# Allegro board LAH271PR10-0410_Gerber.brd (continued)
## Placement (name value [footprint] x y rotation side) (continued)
CT3  0.22U_0201_6.3V6K  [C_0201]  37.16 31.44 270 bottom
CT4  0.22U_0201_6.3V6K  [C_0201]  34.56 31.05 270 bottom
CT5  0.22U_0201_6.3V6K  [C_0201]  33.99 31.05 270 bottom
CT6  0.22U_0201_6.3V6K  [C_0201]  35.37 30.85 90 bottom
CT7  0.22U_0201_6.3V6K  [C_0201]  35.96 30.85 90 bottom
CT8  0.22U_0201_6.3V6K  [C_0201]  32.71 31.13 90 bottom
CT9  0.22U_0201_6.3V6K  [C_0201]  33.28 31.13 90 bottom
CT10  0.22U_0201_6.3V6K  [C_0201]  39.91 41.41 0 bottom
CT11  0.22U_0201_6.3V6K  [C_0201]  39.91 40.84 0 bottom
CT12  0.22U_0201_6.3V6K  [C_0201]  38.39 40.27 0 bottom
CT13  0.22U_0201_6.3V6K  [C_0201]  38.39 39.69 0 bottom
CT14  0.22U_0201_6.3V6K  [C_0201]  39.91 39.12 0 bottom
CT15  0.22U_0201_6.3V6K  [C_0201]  39.91 38.55 0 bottom
CT16  0.22U_0201_6.3V6K  [C_0201]  38.39 37.41 0 bottom
CT17  0.22U_0201_6.3V6K  [C_0201]  38.39 37.98 0 bottom
CT18  0.22U_0201_6.3V6K  [C_0201]  30.27 49.43 90 bottom
CT19  0.22U_0201_6.3V6K  [C_0201]  29.63 49.43 90 bottom
CT20  20P_0402_50V8  [C_0402]  22.21 29.14 180 bottom
CT21  20P_0402_50V8  [C_0402]  23.12 29.14 0 bottom
CT67  1U_0201_10V6M  [C_0201]  27.85 45.38 180 top
CT68  47U_0603_6.3V6M  [C_0603]  40.32 29.14 180 top
CT69  47U_0603_6.3V6M  [C_0603]  40.26 30.74 180 top
CT91  0.47U_0201_25V6M  [C_0201]  5.78 48.77 270 bottom
CT95  0.22U_0201_6.3V6K  [C_0201]  12.31 42.56 180 bottom
CT96  0.22U_0201_6.3V6K  [C_0201]  12.31 43.12 180 bottom
CT97  0.22U_0201_6.3V6K  [C_0201]  14.37 49.8 180 top
CT98  0.22U_0201_6.3V6K  [C_0201]  14.37 49.24 180 top
CT101  0.47U_0201_25V6M  [C_0201]  5.18 48.77 270 bottom
CT102  0.47U_0201_25V6M  [C_0201]  5.15 45.8 270 bottom
CT109  0.47U_0201_25V6M  [C_0201]  5.72 45.79 270 bottom
CT123  0.22U_0201_6.3V6K  [C_0201]  32.09 30.81 270 bottom
CT124  0.22U_0201_6.3V6K  [C_0201]  31.52 30.81 270 bottom
CT125  0.22U_0201_6.3V6K  [C_0201]  29.63 31.73 270 bottom
CT126  0.22U_0201_6.3V6K  [C_0201]  29.05 31.73 270 bottom
CT127  0.22U_0201_6.3V6K  [C_0201]  30.32 31.17 90 bottom
CT128  0.22U_0201_6.3V6K  [C_0201]  30.89 31.17 90 bottom
CT129  0.22U_0201_6.3V6K  [C_0201]  28.05 29.94 90 bottom
CT130  0.22U_0201_6.3V6K  [C_0201]  28.62 29.94 90 bottom
CT178  0.22U_0201_6.3V6K  [C_0201]  31.53 49.07 90 bottom
CT179  0.22U_0201_6.3V6K  [C_0201]  26.22 46.07 90 bottom
CT180  0.22U_0201_6.3V6K  [C_0201]  24.75 46.45 90 bottom
CT181  0.22U_0201_6.3V6K  [C_0201]  27.29 45.54 90 bottom
CT182  0.22U_0201_6.3V6K  [C_0201]  27.87 45.54 90 bottom
CT183  0.22U_0201_6.3V6K  [C_0201]  23.83 46.45 90 bottom
CT184  0.22U_0201_6.3V6K  [C_0201]  30.89 49.07 90 bottom
CT185  0.22U_0201_6.3V6K  [C_0201]  25.65 46.07 90 bottom
CT186  0.22U_0201_6.3V6K  [C_0201]  22.03 46.44 90 bottom
CT187  0.22U_0201_6.3V6K  [C_0201]  22.92 46.44 90 bottom
CT189  12P_0402_50V8J  [C_0402]  9.06 36.43 180 bottom
CT190  82P_0402_50V8J  [C_0402]  8.74 41.23 180 bottom
CT237  0.1U_0201_10V6K  [C_0201]  39.87 50.05 90 top
CT300  1U_0201_6.3V6M  [C_0201]  28.13 37.15 90 top
CT301  1U_0201_6.3V6M  [C_0201]  25.65 38.9 0 top
CT302  1U_0201_6.3V6M  [C_0201]  26.36 36.94 180 top
CT303  1U_0201_6.3V6M  [C_0201]  35.38 40.43 0 top
CT305  1U_0201_6.3V6M  [C_0201]  31.27 37.67 270 top
CT306  1U_0201_6.3V6M  [C_0201]  32.61 37.08 90 top
CT307  1U_0201_6.3V6M  [C_0201]  30.66 38.36 0 top
CT308  1U_0201_6.3V6M  [C_0201]  32.61 38.94 270 top
CT309  1U_0201_6.3V6M  [C_0201]  33.22 39.59 270 top
CT310  1U_0201_6.3V6M  [C_0201]  31.57 40.21 180 top
CT311  1U_0201_6.3V6M  [C_0201]  26.87 39.65 270 top
CT314  1U_0201_6.3V6M  [C_0201]  27.55 36.9 180 top
CT315  1U_0201_6.3V6M  [C_0201]  32.78 40.22 180 top
CT316  1U_0201_6.3V6M  [C_0201]  28.86 38.94 0 top
CT317  1U_0201_6.3V6M  [C_0201]  29.41 39.61 0 top
CT318  1U_0201_6.3V6M  [C_0201]  27.51 39.06 90 top
CT319  1U_0201_6.3V6M  [C_0201]  28.72 37.74 270 top
CT320  1U_0201_6.3V6M  [C_0201]  28.16 38.36 0 top
CT321  1U_0201_6.3V6M  [C_0201]  34.44 38.37 180 top
CT322  1U_0201_6.3V6M  [C_0201]  29.42 37.65 0 top
CT323  10U_0402_6.3V6M  [C_0402]  29.78 46.75 90 top
CT324  10U_0402_6.3V6M  [C_0402]  28.87 46.75 90 top
CT325  10U_0402_6.3V6M  [C_0402]  31.58 46.76 90 top
CT326  10U_0402_6.3V6M  [C_0402]  30.67 46.75 90 top
CT327  1U_0201_6.3V6M  [C_0201]  30.72 41.44 270 top
CT328  1U_0201_6.3V6M  [C_0201]  26.82 40.88 180 top
CT329  10U_0402_6.3V6M  [C_0402]  28.03 42.94 180 top
CT330  10U_0402_6.3V6M  [C_0402]  28 43.85 180 top
CT331  1U_0201_6.3V6M  [C_0201]  28.71 40.24 180 top
CT332  1U_0201_6.3V6M  [C_0201]  27.7 44.61 180 top
CT333  1U_0201_6.3V6M  [C_0201]  30.01 40.19 180 top
CT334  47U_0603_6.3V6M  [C_0603]  31.24 49.96 270 top
CT335  47U_0603_6.3V6M  [C_0603]  28.78 49.97 270 top
CT336  47U_0603_6.3V6M  [C_0603]  30.03 49.95 270 top
CT337  10U_0402_6.3V6M  [C_0402]  34.45 32.19 270 top
CT338  1U_0201_6.3V6M  [C_0201]  35.85 31.99 270 top
CT339  1U_0201_6.3V6M  [C_0201]  36.41 31.98 270 top
CT340  1U_0201_6.3V6M  [C_0201]  34.47 33.26 0 top
CT341  1U_0201_6.3V6M  [C_0201]  35.21 31.99 270 top
CT342  0.1U_0201_10V6K  [C_0201]  49.46 32.91 270 top
CT343  1U_0201_6.3V6M  [C_0201]  52.55 28.88 180 top
CT344  0.1U_0201_10V6K  [C_0201]  55.74 32.69 180 top
CT345  0.1U_0201_10V6K  [C_0201]  47.91 31.6 180 top
CT346  1U_0201_6.3V6M  [C_0201]  55.74 33.33 180 top
CT347  0.1U_0201_10V6K  [C_0201]  56.81 36.62 180 top
CT348  1U_0201_10V6M  [C_0201]  60.73 34.98 180 bottom
CT349  1U_0201_6.3V6M  [C_0201]  56.81 37.18 180 top
CT350  0.1U_0201_10V6K  [C_0201]  54.76 31.4 270 top
CT351  390P_0402_50V7K  [C_0402]  47.32 36.09 180 top
CT352  390P_0402_50V7K  [C_0402]  48.74 28.68 270 top
CT353  390P_0402_50V7K  [C_0402]  48.17 36.01 0 top
CT354  390P_0402_50V7K  [C_0402]  54.59 29.63 0 top
CT355  10U_0603_10V6M  [C_0603]  48.74 32.8 270 bottom
CT356  1U_0201_10V6M  [C_0201]  48.32 32.81 180 top
CT357  10U_0603_10V6M  [C_0603]  53.9 38.64 0 top
CT358  1U_0201_10V6M  [C_0201]  54.32 40.09 90 top
CT359  0.22U_0201_6.3V6K  [C_0201]  9.4 58.08 90 bottom
CT360  0.22U_0201_6.3V6K  [C_0201]  9.96 58.08 90 bottom
CT361  0.47U_0201_25V6M  [C_0201]  11.62 63.52 315 bottom
CT362  0.47U_0201_25V6M  [C_0201]  6.01 61.9 270 bottom
CT363  0.47U_0201_25V6M  [C_0201]  5.79 63.77 270 bottom
CT364  0.47U_0201_25V6M  [C_0201]  5.43 61.9 270 bottom
CT365  0.22U_0201_6.3V6K  [C_0201]  15.47 56.56 90 top
CT366  0.22U_0201_6.3V6K  [C_0201]  16.03 56.56 90 top
CT367  12P_0402_50V8J  [C_0402]  17.35 60.82 45 top
CT368  82P_0402_50V8J  [C_0402]  17.98 60.18 45 top
CT370  0.1U_0201_10V6K  [C_0201]  45.93 27.73 0 bottom
CT371  0.1U_0201_10V6K  [C_0201]  64.26 24.76 90 bottom
CT372  1U_0201_10V6M  [C_0201]  24.13 22.11 270 bottom
CT373  1U_0201_10V6M  [C_0201]  30.75 25.72 90 bottom
CT374  1000P_0402_50V7K  [C_0402]  29.57 23.37 270 bottom
CT375  0.01U_0402_16V7K  [C_0402]  36.32 28.19 180 top
CT376  0.1U_0201_25V6K  [C_0201]  38.47 28.97 0 bottom
CT377  0.1U_0201_10V6K  [C_0201]  48.59 28.58 90 bottom
CT378  1000P_0201_25V7K  [C_0201]  43.93 27.85 90 bottom
CT379  0.1U_0201_10V6K  [C_0201]  60.17 20.81 270 bottom
CT380  1000P_0201_25V7K  [C_0201]  58.86 20.2 90 bottom
CT383  0.1U_0201_10V6K  [C_0201]  177.68 18.55 270 bottom
CT384  0.1U_0201_10V6K  [C_0201]  179.59 24.86 90 bottom
CT389  0.1U_0201_10V6K  [C_0201]  121.91 14.52 0 top
CT390  0.33U_0201_25V6K  [C_0201]  14.37 49.24 180 bottom
CT391  0.33U_0201_25V6K  [C_0201]  14.37 49.8 180 bottom
CT392  0.33U_0201_25V6K  [C_0201]  11.72 43.12 0 top
CT393  0.33U_0201_25V6K  [C_0201]  11.72 42.56 0 top
CT394  0.33U_0201_25V6K  [C_0201]  16.03 56.56 90 bottom
CT395  0.33U_0201_25V6K  [C_0201]  15.47 56.56 90 bottom
CT396  0.33U_0201_25V6K  [C_0201]  9.96 58.67 270 top
CT397  0.33U_0201_25V6K  [C_0201]  9.4 58.67 270 top
CV1  0.1U_0201_10V6K  [C_0201]  104.68 47.45 90 bottom
CV2  0.1U_0201_10V6K  [C_0201]  103.79 47.45 90 bottom
CV3  0.1U_0201_10V6K  [C_0201]  108.59 43.25 90 bottom
CV4  0.1U_0201_10V6K  [C_0201]  109.48 43.25 90 bottom
CV5  0.1U_0201_10V6K  [C_0201]  110.41 43.24 90 bottom
CV6  0.1U_0201_10V6K  [C_0201]  111.3 43.24 90 bottom
CV13  1U_0603_50V6K  [C_0603]  84.86 38.29 270 top
CV14  0.01U_0402_50V7K  [C_0402]  84.85 41.63 90 top
CV15  0.1U_0402_50V7K  [C_0402]  86.81 43.28 180 top
CV16  10U_0402_6.3V6M  [C_0402]  95.64 39.67 270 top
CV20  0.1U_0201_25V6K  [C_0201]  101.45 39.79 270 top
CV60  0.01U_0402_16V7K  [C_0402]  194.28 122.27 270 bottom
CV61  0.01U_0402_16V7K  [C_0402]  193.13 111.75 0 bottom
CV62  0.1U_0201_25V6K  [C_0201]  188.94 121.39 270 bottom
CV63  0.1U_0201_25V6K  [C_0201]  193.58 114.79 180 bottom
CV64  0.1U_0201_25V6K  [C_0201]  187.44 112.12 180 top
CV65  0.1U_0201_10V6K  [C_0201]  196.43 114.78 180 top
CV66  0.1U_0201_10V6K  [C_0201]  196.43 115.67 180 top
CV67  0.1U_0201_10V6K  [C_0201]  198.21 116.1 180 top
CV68  0.1U_0201_10V6K  [C_0201]  198.21 116.99 180 top
CV69  0.1U_0201_10V6K  [C_0201]  196.43 117.68 180 top
CV70  0.1U_0201_10V6K  [C_0201]  196.43 118.57 180 top
CV71  0.1U_0201_10V6K  [C_0201]  198.16 119.4 180 top
CV72  0.1U_0201_10V6K  [C_0201]  198.16 120.29 180 top
CV73  0.1U_0201_10V6K  [C_0201]  192.19 124.53 270 top
CV74  0.1U_0201_10V6K  [C_0201]  191.3 124.53 270 top
CV75  2.2U_0402_6.3V6M  [C_0402]  195.68 121.51 0 top
CV427  0.22U_0201_6.3V6K  [C_0201]  185.92 97.11 0 bottom
CV428  0.22U_0201_6.3V6K  [C_0201]  185.92 96.22 0 bottom
CV429  0.22U_0201_6.3V6K  [C_0201]  183.55 97.62 0 bottom
CV430  0.22U_0201_6.3V6K  [C_0201]  183.55 98.51 0 bottom
CV431  0.22U_0201_6.3V6K  [C_0201]  185.92 99.67 0 bottom
CV432  0.22U_0201_6.3V6K  [C_0201]  185.92 98.79 0 bottom
CV433  0.22U_0201_6.3V6K  [C_0201]  183.38 100.1 0 bottom
CV434  0.22U_0201_6.3V6K  [C_0201]  183.38 100.99 0 bottom
CV435  0.22U_0201_6.3V6K  [C_0201]  185.92 101.22 0 bottom
CV436  0.22U_0201_6.3V6K  [C_0201]  185.92 102.11 0 bottom
CV437  0.22U_0201_6.3V6K  [C_0201]  183.38 102.54 0 bottom
CV438  0.22U_0201_6.3V6K  [C_0201]  183.38 103.43 0 bottom
CV439  0.22U_0201_6.3V6K  [C_0201]  185.92 104.57 0 bottom
CV440  0.22U_0201_6.3V6K  [C_0201]  185.92 103.68 0 bottom
CV441  0.22U_0201_6.3V6K  [C_0201]  183.38 105.89 0 bottom
CV442  0.22U_0201_6.3V6K  [C_0201]  183.38 105 0 bottom
CV443  0.22U_0201_6.3V6K  [C_0201]  185.92 107.16 0 bottom
CV444  0.22U_0201_6.3V6K  [C_0201]  185.92 106.23 0 bottom
CV445  0.22U_0201_6.3V6K  [C_0201]  183.38 108.33 0 bottom
CV446  0.22U_0201_6.3V6K  [C_0201]  183.38 107.44 0 bottom
CV447  0.22U_0201_6.3V6K  [C_0201]  185.92 108.75 0 bottom
CV448  0.22U_0201_6.3V6K  [C_0201]  185.92 109.66 0 bottom
CV449  0.22U_0201_6.3V6K  [C_0201]  183.38 110.8 0 bottom
CV450  0.22U_0201_6.3V6K  [C_0201]  183.38 109.91 0 bottom
CV451  0.22U_0201_6.3V6K  [C_0201]  185.92 111.44 0 bottom
CV452  0.22U_0201_6.3V6K  [C_0201]  185.92 112.33 0 bottom
CV453  0.22U_0201_6.3V6K  [C_0201]  183.38 112.55 0 bottom
CV454  0.22U_0201_6.3V6K  [C_0201]  183.38 113.42 0 bottom
CV455  0.22U_0201_6.3V6K  [C_0201]  185.69 114.74 0 bottom
CV456  0.22U_0201_6.3V6K  [C_0201]  185.69 113.85 0 bottom
CV457  0.22U_0201_6.3V6K  [C_0201]  183.38 114.99 0 bottom
CV458  0.22U_0201_6.3V6K  [C_0201]  183.38 115.88 0 bottom
CV805  0.1U_0201_16V6K  [C_0201]  173.29 92.32 90 bottom
CV806  10U_0402_6.3V6M  [C_0402]  180.36 84.3 0 bottom
CV809  0.1U_0201_10V6K  [C_0201]  187.03 102.76 270 top
CV810  0.1U_0201_10V6K  [C_0201]  183.95 86.3 90 top
CV811  0.1U_0201_10V6K  [C_0201]  181.85 94.9 90 top
CV812  1000P_0402_50V7K  [C_0402]  185.83 90.09 90 top
CV813  4.7U_0402_6.3V6M  [C_0402]  117.46 36.76 90 top
CV814  0.1U_0201_10V6K  [C_0201]  106.91 40.23 270 top
CV815  0.1U_0201_10V6K  [C_0201]  106.93 37.97 90 top
CV816  0.1U_0201_10V6K  [C_0201]  106.96 35.84 90 top
CV817  0.1U_0201_10V6K  [C_0201]  115.3 39.92 270 top
CV818  2.2U_0402_6.3V6M  [C_0402]  97.92 37.37 0 bottom
CV819  0.1U_0201_10V6K  [C_0201]  110.47 32.32 90 bottom
CV820  0.1U_0201_10V6K  [C_0201]  109.6 32.32 90 bottom
CV821  0.1U_0201_10V6K  [C_0201]  108.65 31.58 90 bottom
CV822  0.1U_0201_10V6K  [C_0201]  107.76 31.58 90 bottom
CV823  0.1U_0201_10V6K  [C_0201]  106.83 32.19 90 bottom
CV824  0.1U_0201_10V6K  [C_0201]  105.94 32.19 90 bottom
CV825  0.1U_0201_10V6K  [C_0201]  104.95 31.71 90 bottom
CV826  0.1U_0201_10V6K  [C_0201]  104.09 31.71 90 bottom
CV827  0.1U_0201_10V6K  [C_0201]  103.9 40.88 0 bottom
CV828  0.1U_0201_10V6K  [C_0201]  103.88 39.99 0 bottom
CV829  0.1U_0201_10V6K  [C_0201]  118.22 33.87 270 bottom
CV830  0.1U_0201_10V6K  [C_0201]  119.11 33.87 270 bottom
CV831  0.1U_0201_10V6K  [C_0201]  116.03 31.58 90 bottom
CV832  0.1U_0201_10V6K  [C_0201]  115.16 31.58 90 bottom
CV833  0.1U_0201_10V6K  [C_0201]  114.14 32.32 90 bottom
CV834  0.1U_0201_10V6K  [C_0201]  113.26 32.32 90 bottom
CV835  0.1U_0201_10V6K  [C_0201]  112.29 31.58 90 bottom
CV836  0.1U_0201_10V6K  [C_0201]  111.41 31.58 90 bottom
CV837  0.1U_0201_10V6K  [C_0201]  103.85 39.02 0 bottom
CV838  0.1U_0201_10V6K  [C_0201]  103.85 38.14 0 bottom
CV839  82P_0402_50V8J  [C_0402]  89.56 43.28 180 top
CV840  82P_0402_50V8J  [C_0402]  91.01 40.09 0 top
CV841  22P_0402_50V8J  [C_0402]  89.53 41.43 90 top
CV842  100P_0402_50V8J  [C_0402]  98.34 35.27 180 top
CV843  100P_0402_50V8J  [C_0402]  101.51 36.26 270 top
CV844  0.1U_0201_10V6K  [C_0201]  134.05 45.67 90 top
CV845  0.1U_0201_10V6K  [C_0201]  112.22 43.28 90 bottom
CV846  0.1U_0201_10V6K  [C_0201]  113.11 43.28 90 bottom
CV847  0.1U_0201_10V6K  [C_0201]  114.05 43.32 90 bottom
CV848  0.1U_0201_10V6K  [C_0201]  114.94 43.32 90 bottom
CV849  0.1U_0402_50V7K  [C_0402]  91.92 39.17 180 top
CV850  0.1U_0201_25V6K  [C_0201]  77.73 33.05 270 top
CV851  10P_0402_50V8J  [C_0402]  93.43 22.56 0 bottom
CV852  82P_0402_50V8J  [C_0402]  94.33 21.66 180 bottom
CV853  2.2P_0402_50V8C  [C_0402]  94.36 23.47 180 bottom
CV854  4.7U_0402_6.3V6M  [C_0402]  73.17 33.03 0 bottom
CV855  0.1U_0201_10V6K  [C_0201]  55.76 33.89 180 top
CV856  0.1U_0201_10V6K  [C_0201]  65.72 28.5 180 top
CV857  0.01U_0402_16V7K  [C_0402]  65.92 26.84 180 top
CV858  0.01U_0402_16V7K  [C_0402]  65.91 27.74 180 top
CV860  0.22U_0201_6.3V6K  [C_0201]  70.69 37.92 90 top
CV861  0.22U_0201_6.3V6K  [C_0201]  69.98 37.92 90 top
CV862  0.22U_0201_6.3V6K  [C_0201]  69.11 37.9 90 top
CV863  0.22U_0201_6.3V6K  [C_0201]  68.42 37.89 90 top
CV864  0.22U_0201_6.3V6K  [C_0201]  67.55 39.76 90 top
CV865  0.22U_0201_6.3V6K  [C_0201]  66.66 39.76 90 top
CV866  0.22U_0201_6.3V6K  [C_0201]  65.72 39.79 90 top
CV867  0.22U_0201_6.3V6K  [C_0201]  64.83 39.79 90 top
CV868  0.22U_0201_6.3V6K  [C_0201]  63.87 39.43 90 top
CV869  0.22U_0201_6.3V6K  [C_0201]  62.98 39.43 90 top
CV870  0.22U_0201_6.3V6K  [C_0201]  62.09 39.43 90 top
CV871  0.22U_0201_6.3V6K  [C_0201]  61.2 39.43 90 top
CV872  0.22U_0201_6.3V6K  [C_0201]  60.31 39.43 90 top
CV873  0.22U_0201_6.3V6K  [C_0201]  59.42 39.43 90 top
CV874  0.22U_0201_6.3V6K  [C_0201]  58.53 39.43 90 top
CV875  0.22U_0201_6.3V6K  [C_0201]  57.64 39.43 90 top
CV876  0.1U_0201_10V6K  [C_0201]  75.05 32.35 180 top
CV877  0.1U_0201_10V6K  [C_0201]  75.05 31.46 180 top
CV878  4.7U_0402_6.3V6M  [C_0402]  153.62 46.98 90 top
CV879  0.1U_0201_10V6K  [C_0201]  153.74 45.47 270 bottom
CV880  0.1U_0201_10V6K  [C_0201]  152.86 45.47 270 bottom
CV881  0.01U_0402_16V7K  [C_0402]  152.88 46.57 90 bottom
CV882  0.01U_0402_16V7K  [C_0402]  153.76 46.57 90 bottom
CV883  0.22U_0201_6.3V6K  [C_0201]  152.35 48.37 90 top
CV884  0.22U_0201_6.3V6K  [C_0201]  151.46 48.37 90 top
CV885  0.22U_0201_6.3V6K  [C_0201]  150.57 48.37 90 top
CV886  0.22U_0201_6.3V6K  [C_0201]  149.68 48.37 90 top
CV887  0.22U_0201_6.3V6K  [C_0201]  148.79 48.37 90 top
CV888  0.22U_0201_6.3V6K  [C_0201]  147.9 48.37 90 top
CV889  0.22U_0201_6.3V6K  [C_0201]  147.01 48.37 90 top
CV890  0.22U_0201_6.3V6K  [C_0201]  146.12 48.37 90 top
CV891  0.22U_0201_6.3V6K  [C_0201]  145.24 48.37 90 top
CV892  0.22U_0201_6.3V6K  [C_0201]  144.35 48.37 90 top
CV893  0.22U_0201_6.3V6K  [C_0201]  143.46 48.37 90 top
CV894  0.22U_0201_6.3V6K  [C_0201]  142.57 48.37 90 top
CV895  0.22U_0201_6.3V6K  [C_0201]  141.68 48.37 90 top
CV896  0.22U_0201_6.3V6K  [C_0201]  140.79 48.37 90 top
CV897  0.22U_0201_6.3V6K  [C_0201]  139.9 48.37 90 top
CV898  0.22U_0201_6.3V6K  [C_0201]  139.01 48.37 90 top
CV901  0.01U_0402_16V7K  [C_0402]  61.26 31.69 90 bottom
CV902  10U_0402_6.3V6M  [C_0402]  174.83 79.21 270 bottom
CV903  0.1U_0201_10V6K  [C_0201]  175.62 78.99 270 bottom
CV908  0.1U_0201_10V6K  [C_0201]  67.05 36.58 270 bottom
CV909  0.1U_0201_10V6K  [C_0201]  62.38 36.83 0 bottom
CV910  4.7U_0402_6.3V6M  [C_0402]  62.21 37.91 0 bottom
CV911  0.01U_0402_16V7K  [C_0402]  70.38 29.33 270 bottom
CV912  0.01U_0402_16V7K  [C_0402]  69.06 30.65 90 bottom
CV913  0.1U_0201_10V6K  [C_0201]  67.86 30.84 90 bottom
CV914  4.7U_0402_6.3V6M  [C_0402]  71.54 29.33 270 bottom
CV915  0.1U_0201_10V6K  [C_0201]  66.65 30.84 90 bottom
CV916  0.01U_0402_16V7K  [C_0402]  65.33 30.57 90 bottom
CV917  1U_0201_10V6M  [C_0201]  65.11 29.77 180 bottom
CV918  0.1U_0201_10V6K  [C_0201]  64.47 30.7 90 bottom
CV919  4.7U_0402_6.3V6M  [C_0402]  64.98 28.73 180 bottom
CV920  0.01U_0402_16V7K  [C_0402]  152.85 40.88 0 bottom
CV921  0.01U_0402_16V7K  [C_0402]  152.03 41.36 180 bottom
CV922  0.1U_0201_10V6K  [C_0201]  140.95 38.85 270 bottom
CV923  0.1U_0201_10V6K  [C_0201]  139.98 39.5 180 top
CV924  4.7U_0402_6.3V6M  [C_0402]  140.88 37.98 270 top
CV925  0.01U_0402_16V7K  [C_0402]  147.47 45.72 270 bottom
CV926  0.01U_0402_16V7K  [C_0402]  141.7 45.1 0 bottom
CV927  0.1U_0201_10V6K  [C_0201]  148.64 45.73 270 bottom
CV928  4.7U_0402_6.3V6M  [C_0402]  139.58 45.27 180 top
CV929  0.1U_0201_10V6K  [C_0201]  141.91 45.89 0 bottom
CV930  0.01U_0402_16V7K  [C_0402]  145.14 39.79 90 bottom
CV931  0.01U_0402_16V7K  [C_0402]  143.97 39.78 90 bottom
CV932  0.1U_0201_10V6K  [C_0201]  150.77 37.96 180 bottom
CV933  4.7U_0402_6.3V6M  [C_0402]  151.78 37.94 0 top
CV934  0.1U_0201_10V6K  [C_0201]  151.71 37.98 0 bottom
CV935  0.01U_0402_16V7K  [C_0402]  144.07 38.5 180 bottom
CV936  4.7U_0402_6.3V6M  [C_0402]  146.2 36.85 0 top
CV937  0.1U_0201_10V6K  [C_0201]  143.94 37.48 180 bottom
CV938  1U_0201_10V6M  [C_0201]  145.16 36.99 270 bottom
CV939  0.1U_0201_10V6K  [C_0201]  72.45 34.21 180 bottom
CV940  1U_0201_10V6M  [C_0201]  72.45 35.69 180 bottom
CV941  0.1U_0201_10V6K  [C_0201]  153.05 45.8 0 top
CV942  1U_0201_10V6M  [C_0201]  153.05 44.91 0 top
CV943  0.1U_0201_10V6K  [C_0201]  154.82 42.98 180 top
CV944  0.1U_0201_10V6K  [C_0201]  154.82 43.88 180 top
CV945  0.1U_0201_10V6K  [C_0201]  74.18 34.15 180 top
CV946  0.1U_0201_10V6K  [C_0201]  74.18 33.28 180 top
CV947  0.01U_0402_16V7K  [C_0402]  63.36 31.68 90 bottom
CV948  0.1U_0201_10V6K  [C_0201]  62.13 31.95 90 bottom
CV949  0.01U_0402_16V7K  [C_0402]  69.99 36.82 270 bottom
CV950  4.7U_0402_6.3V6M  [C_0402]  71.11 31.21 180 bottom
CV951  0.1U_0201_10V6K  [C_0201]  71.7 32.09 90 bottom
CV952  0.01U_0402_16V7K  [C_0402]  62.25 35.97 0 bottom
CV953  0.1U_0201_25V6K  [C_0201]  76.63 25.05 270 top
CV954  0.1U_0201_25V6K  [C_0201]  75.73 55.97 180 bottom
CV955  82P_0402_50V8J  [C_0402]  116.23 39.92 270 top
CV956  82P_0402_50V8J  [C_0402]  176.41 79.21 270 bottom
CV957  82P_0402_50V8J  [C_0402]  174.11 92.07 90 bottom
CZ10  0.1U_0201_10V6K  [C_0201]  308.18 2.52 90 top
CZ11  0.1U_0201_10V6K  [C_0201]  309.08 2.52 90 top
CZ12  0.1U_0201_25V6K  [C_0201]  324.91 7.1 90 bottom
CZ13  0.1U_0201_25V6K  [C_0201]  325.8 7.1 90 bottom
CZ17  0.047U_0201_10V6K  [C_0201]  282.01 10.39 180 bottom
CZ18  0.047U_0201_10V6K  [C_0201]  282.01 8.72 180 bottom
CZ19  33P_0402_50V8J  [C_0402]  282.15 9.49 180 bottom
CZ20  22U_0603_6.3V6M  [C_0603]  308.15 6.14 270 top
CZ21  33P_0402_50V8J  [C_0402]  282.12 7.97 180 bottom
CZ28  0.1U_0201_10V6K  [C_0201]  298.21 8.04 0 top
CZ29  0.1U_0201_10V6K  [C_0201]  298.21 7.03 0 top
CZ37  1U_0201_10V6M  [C_0201]  345.49 49.22 90 bottom
CZ38  33P_0402_50V8J  [C_0402]  347.66 49.24 90 bottom
CZ39  33P_0402_50V8J  [C_0402]  348.76 49.24 90 bottom
CZ40  33P_0402_50V8J  [C_0402]  346.7 49.22 90 bottom
CZ50  0.1U_0201_25V6K  [C_0201]  115.88 23.35 90 top
CZ51  0.1U_0201_10V6K  [C_0201]  117.52 27.37 0 top
CZ52  10U_0402_6.3V6M  [C_0402]  113.88 26.65 270 top
CZ53  0.1U_0201_10V6K  [C_0201]  121.17 24.36 180 bottom
CZ54  0.1U_0201_10V6K  [C_0201]  121.17 23.07 180 bottom
CZ55  10U_0603_10V6M  [C_0603]  122.94 19.7 270 top
CZ56  0.1U_0201_25V6K  [C_0201]  124.95 22.3 180 top
CZ57  12P_0402_50V8J  [C_0402]  117.14 16.54 90 top
CZ58  68P_0402_50V8J  [C_0402]  116.25 16.54 90 top
CZ59  12P_0402_50V8J  [C_0402]  122.69 15.6 180 top
CZ60  68P_0402_50V8J  [C_0402]  123.65 16.99 270 top
CZ61  0.047U_0201_10V6K  [C_0201]  183.11 16.4 90 bottom
CZ62  68P_0402_50V8J  [C_0402]  137.66 13.87 270 bottom
CZ63  68P_0402_50V8J  [C_0402]  136.57 13.86 270 bottom
CZ64  0.1U_0201_10V6K  [C_0201]  194.27 7.68 270 top
CZ66  0.1U_0201_10V6K  [C_0201]  194.27 5.01 90 top
CZ67  0.1U_0201_10V6K  [C_0201]  171.59 8.25 270 top
CZ68  0.1U_0201_10V6K  [C_0201]  194.02 10.34 270 top
CZ69  68P_0402_50V8J  [C_0402]  193.54 7.43 270 top
CZ71  68P_0402_50V8J  [C_0402]  193.48 4.67 90 top
CZ72  68P_0402_50V8J  [C_0402]  165.15 7.15 90 top
CZ73  68P_0402_50V8J  [C_0402]  194.78 10.44 270 top
CZ75  10U_0402_6.3V6M  [C_0402]  117.47 22.96 270 bottom
CZ80  10P_0402_50V8J  [C_0402]  278.4 8.39 0 top
CZ81  10P_0402_50V8J  [C_0402]  278.37 9.58 0 top
CZ82  0.1U_0201_10V6K  [C_0201]  119.78 9 270 top
CZ90  0.1U_0201_25V6K  [C_0201]  288.38 12.69 0 bottom
CZ91  0.1U_0201_25V6K  [C_0201]  291.06 12.69 180 bottom
CZ92  0.1U_0201_25V6K  [C_0201]  291.89 12.7 0 bottom
CZ93  0.1U_0201_10V6K  [C_0201]  313.99 43.48 270 top
CZ100  1U_0201_10V6M  [C_0201]  193.33 89.01 270 top
CZ101  0.1U_0201_10V6K  [C_0201]  193.01 86.74 270 top
CZ102  1U_0201_10V6M  [C_0201]  278.58 85.2 270 top
CZ105  1U_0201_10V6M  [C_0201]  189.89 92.52 90 top
CZ106  0.1U_0201_10V6K  [C_0201]  190.41 96.29 90 top
CZ120  0.1U_0201_10V6K  [C_0201]  335.61 26.62 0 bottom
CZ121  470P_0402_50V7K  [C_0402]  335.6 27.51 0 bottom
CZ129  0.1U_0201_10V6K  [C_0201]  327.28 32.17 0 top
CZ130  470P_0402_50V7K  [C_0402]  328.61 32.34 0 top
CZ157  330U_D2E_6.3VM_R25M  [C_D2E]  319.37 19.12 0 top
CZ164  330U_D2E_6.3VM_R25M  [C_D2E]  305.2 8.94 270 top
CZ198  100P_0402_50V8J  [C_0402]  280.25 7.04 0 bottom
CZ199  0.1U_0201_10V6K  [C_0201]  276.53 86.59 0 top
CZ200  0.1U_0201_10V6K  [C_0201]  278.5 80.19 270 top
CZ218  2.2U_0201_6.3V6M  [C_0201]  135.98 11.73 0 top
CZ505  10U_0402_6.3V6M  [C_0402]  81.99 55.4 270 bottom
CZ506  10U_0402_6.3V6M  [C_0402]  298.36 53.73 90 top
CZ507  0.1U_0201_25V6K  [C_0201]  295.77 53.3 90 top
CZ508  0.1U_0201_25V6K  [C_0201]  83.26 55.3 270 bottom
CZ509  0.1U_0201_25V6K  [C_0201]  101.9 48.36 270 bottom
CZ510  10U_0402_6.3V6M  [C_0402]  96.56 39.67 270 top
CZ511  0.1U_0201_25V6K  [C_0201]  95.52 42.84 270 bottom
CZ512  10P_0402_50V8J  [C_0402]  96.41 41.91 90 bottom
CZ513  0.1U_0201_10V6K  [C_0201]  186.06 86.18 0 bottom
CZ514  0.1U_0201_10V6K  [C_0201]  180.33 72.61 180 bottom
CZ515  470P_0402_50V7K  [C_0402]  182.41 70.77 90 bottom
CZ516  470P_0402_50V7K  [C_0402]  186.77 88.38 180 bottom
CZ517  470P_0402_50V7K  [C_0402]  186.75 87.03 180 bottom
CZ518  0.1U_0201_10V6K  [C_0201]  186.03 89.2 0 bottom
CZ519  0.1U_0201_10V6K  [C_0201]  338.61 46.55 90 top
CZ520  0.1U_0201_10V6K  [C_0201]  106.69 27.52 90 bottom
CZ521  470P_0402_50V7K  [C_0402]  104.13 27.82 270 bottom
CZ522  1000P_0402_50V7K  [C_0402]  340.39 47.33 270 top
CZ523  470P_0402_50V7K  [C_0402]  339.5 47.33 270 top
CZ524  0.1U_0201_10V6K  [C_0201]  341.34 46.61 90 top
CZ525  0.1U_0201_25V6K  [C_0201]  107.45 12.55 0 top
CZ526  0.47U_0402_25V6K  [C_0402]  93.41 12.73 270 top
CZ527  0.1U_0201_10V6K  [C_0201]  309.2 4.44 90 top
CZ528  82P_0402_50V8J  [C_0402]  186.81 91 270 bottom
CZ529  82P_0402_50V8J  [C_0402]  185.84 85.31 0 bottom
CZ530  0.1U_0201_10V6K  [C_0201]  317.52 20.26 90 bottom
CZ531  10U_0402_6.3V6M  [C_0402]  335.9 20.72 90 bottom
CZ532  0.01U_0402_16V7K  [C_0402]  336.79 20.72 90 bottom
CZ533  0.01U_0402_16V7K  [C_0402]  316.18 20.2 90 bottom
CZ534  0.1U_0201_10V6K  [C_0201]  316.92 20.29 90 bottom
CZ535  10U_0402_6.3V6M  [C_0402]  317.95 22.34 0 top
CZ536  0.1U_0201_25V6K  [C_0201]  333.99 6.5 90 bottom
CZ537  0.1U_0201_25V6K  [C_0201]  333.1 6.5 90 bottom
CZ538  0.1U_0201_25V6K  [C_0201]  332.2 6.69 90 bottom
CZ539  0.1U_0201_25V6K  [C_0201]  331.31 6.69 90 bottom
CZ540  0.1U_0201_10V6K  [C_0201]  326.72 26.03 90 top
CZ541  100P_0402_50V8J  [C_0402]  317.38 43.45 90 top
CZ542  0.01U_0402_16V7K  [C_0402]  319.2 20.13 90 bottom
CZ543  0.01U_0402_16V7K  [C_0402]  318.28 20.12 90 bottom
CZ544  0.1U_0201_25V6K  [C_0201]  194.32 88.09 270 top
CZ545  82P_0402_50V8J  [C_0402]  107.28 13.43 0 top
DA1  AZ5125-02S.R7G_SOT23-3  [AZ5125-02SPR7G_SOT23-3]  356.5 23.73 0 bottom
DA2  AZ5125-02S.R7G_SOT23-3  [AZ5125-02SPR7G_SOT23-3]  357.53 14.64 180 bottom
DA3  AZ5123-02S.R7G_SOT23-3  [AZ5123-02SPR7G_SOT23-3]  355.5 14.7 0 top
DA6  AZ5125-02S.R7G_SOT23-3  [AZ5125-02SPR7G_SOT23-3]  326.62 10.79 90 top
DA7  AZ5125-02S.R7G_SOT23-3  [AZ5125-02SPR7G_SOT23-3]  326.62 14.76 90 top
DA8  -  [RB751S-40_SOD523-2]  338.15 22.13 270 top
DE2  -  [RB751S-40_SOD523-2]  148.61 31.65 270 top
DH1  -  [RB751S-40_SOD523-2]  152.84 24.18 180 bottom
DH2  -  [RB751S-40_SOD523-2]  151.21 22.89 0 bottom
DI1  -  [AZ1045-04F_DFN2510P10E-10-9]  355.78 55.35 270 bottom
DI2  -  [PESD5V0U2BT_SOT23-3]  356.2 53.37 90 top
DI3  -  [PESD5V0U2BT_SOT23-3]  354.87 36 0 top
DI6  -  [AZ1045-04F_DFN2510P10E-10-9]  355.72 33.91 270 top
DT4  AZ4024_02S_R7G_SOT23-3  [PESD24VS2UT_SOT23-3]  11.77 38.83 270 bottom
DT5  AZ5B75-01B.R7G_CSP0603P2Y2  [AZ5B75-01BPR7G_CSP0603P2Y2]  12.99 42.51 270 bottom
DT6  AZ5B75-01B.R7G_CSP0603P2Y2  [AZ5B75-01BPR7G_CSP0603P2Y2]  12.99 43.18 90 bottom
DT7  -  [AZ1045-04F_DFN2510P10E-10-9]  12.21 45.49 90 bottom
DT8  -  [AZ1045-04F_DFN2510P10E-10-9]  13.09 45.49 90 top
DT9  AZ5B75-01B.R7G_CSP0603P2Y2  [AZ5B75-01BPR7G_CSP0603P2Y2]  15.05 49.17 270 bottom
DT10  AZ5B75-01B.R7G_CSP0603P2Y2  [AZ5B75-01BPR7G_CSP0603P2Y2]  15.05 49.84 90 bottom
DT11  -  [AZ1045-04F_DFN2510P10E-10-9]  11.65 58.89 0 bottom
DT12  -  [AZ1045-04F_DFN2510P10E-10-9]  11.65 58.01 0 top
DT13  AZ5B75-01B.R7G_CSP0603P2Y2  [AZ5B75-01BPR7G_CSP0603P2Y2]  12.99 42.51 270 top
DT14  AZ5B75-01B.R7G_CSP0603P2Y2  [AZ5B75-01BPR7G_CSP0603P2Y2]  12.99 43.18 90 top
DT17  AZ5B75-01B.R7G_CSP0603P2Y2  [AZ5B75-01BPR7G_CSP0603P2Y2]  15.05 49.84 90 top
DT18  AZ5B75-01B.R7G_CSP0603P2Y2  [AZ5B75-01BPR7G_CSP0603P2Y2]  15.05 49.17 270 top
DT43  AZ5B75-01B.R7G_CSP0603P2Y2  [AZ5B75-01BPR7G_CSP0603P2Y2]  13.21 51.87 270 bottom
DT44  AZ5B75-01B.R7G_CSP0603P2Y2  [AZ5B75-01BPR7G_CSP0603P2Y2]  13.21 51.87 270 top
DT45  AZ5B75-01B.R7G_CSP0603P2Y2  [AZ5B75-01BPR7G_CSP0603P2Y2]  13.21 52.54 90 top
DT48  AZ5B75-01B.R7G_CSP0603P2Y2  [AZ5B75-01BPR7G_CSP0603P2Y2]  13.21 52.54 90 bottom
DT51  AZ5B75-01B.R7G_CSP0603P2Y2  [AZ5B75-01BPR7G_CSP0603P2Y2]  15.42 55.88 180 bottom
DT52  AZ5B75-01B.R7G_CSP0603P2Y2  [AZ5B75-01BPR7G_CSP0603P2Y2]  16.08 55.88 0 top
DT53  AZ5B75-01B.R7G_CSP0603P2Y2  [AZ5B75-01BPR7G_CSP0603P2Y2]  16.08 55.88 0 bottom
DT54  AZ5B75-01B.R7G_CSP0603P2Y2  [AZ5B75-01BPR7G_CSP0603P2Y2]  15.42 55.88 180 top
DT59  AZ4024_02S_R7G_SOT23-3  [PESD24VS2UT_SOT23-3]  18.29 57.12 315 top
DT60  -  [RB520SM-30T2R_EMD2-2]  32.01 23.99 270 bottom
DT62  -  [RB520SM-30T2R_EMD2-2]  30.79 23.99 270 bottom
DT63  -  [RB520SM-30T2R_EMD2-2]  32.8 26.13 0 bottom
DT64  -  [RB520SM-30T2R_EMD2-2]  32.79 27.36 0 bottom
DV3  -  [BAT54CW_SOT323-3]  133.06 43.67 90 top
DV4  AZ5125-02S.R7G_SOT23-3  [AZ5125-02SPR7G_SOT23-3]  99.01 39.1 180 top
DV30  -  [PESD5V0U2BT_SOT23-3]  80.14 32.25 0 top
DV32  -  [RB751VM-40TE-17_SOD323-2]  192.88 100.81 180 top
DV33  -  [RB751VM-40TE-17_SOD323-2]  192.86 99.19 180 top
DV34  -  [RB751VM-40TE-17_SOD323-2]  184.53 88.76 90 top
DV35  -  [RB751VM-40TE-17_SOD323-2]  113.19 47.73 90 bottom
DV36  -  [RB751VM-40TE-17_SOD323-2]  111.59 47.71 90 bottom
DV37  -  [RB751VM-40TE-17_SOD323-2]  114.87 47.67 90 bottom
DV38  -  [RB751VM-40TE-17_SOD323-2]  132.14 48.93 180 top
DV39  -  [RB751VM-40TE-17_SOD323-2]  132.14 47.3 180 top
DV40  -  [RB751VM-40TE-17_SOD323-2]  134.79 49.21 0 top
DV41  -  [PESD5V0U2BT_SOT23-3]  104.39 38.77 180 top
DV42  -  [RB751VM-40TE-17_SOD323-2]  133.69 41.58 0 top
DV43  -  [RB751VM-40TE-17_SOD323-2]  192.88 102.39 180 top
DV44  -  [RB751VM-40TE-17_SOD323-2]  186.57 100.59 180 top
DZ1  -  [RB751S-40_SOD523-2]  331.69 22.25 270 bottom
DZ2  -  [RB751S-40_SOD523-2]  330.09 22.23 270 bottom
DZ5  -  [RB751S-40_SOD523-2]  283.38 7.34 90 bottom
DZ6  -  [RB751S-40_SOD523-2]  284.63 7.35 90 bottom
DZ8  -  [RB751S-40_SOD523-2]  181.07 16.16 90 bottom
DZ9  -  [BAT54CW_SOT323-3]  137.84 38.79 0 top
DZ12  -  [RB751S40T1G_SOD523-2]  134.93 13.55 270 top
DZ20  BZX384-B5V6 SC76-2  [RB751V40_SC76-2]  80.42 54.85 270 bottom
DZ21  BZX384-B5V6 SC76-2  [RB751V40_SC76-2]  301.65 53.08 90 top
FD1  FIDUCIAL MARK~D  [FIDUCIAL_C40M80]  367.94 65.51 180 bottom
FD2  FIDUCIAL MARK~D  [FIDUCIAL_C40M80]  367.94 65.51 0 top
FD3  FIDUCIAL MARK~D  [FIDUCIAL_C40M80]  22.57 51.25 0 top
FD4  FIDUCIAL MARK~D  [FIDUCIAL_C40M80]  13.63 8.55 180 bottom
FD5  FIDUCIAL MARK~D  [FIDUCIAL_C40M80]  123.49 41.96 0 top
FD6  FIDUCIAL MARK~D  [FIDUCIAL_C40M80]  225.86 4.31 180 bottom
FV1  1A_65V_T0603FF1000TM  [F_T0603FF1000TM]  88.76 36.78 0 top
FV3  1A_65V_T0603FF1000TM  [F_T0603FF1000TM]  78.53 29.38 0 top
FZ1  1A_65V_T0603FF1000TM  [F_T0603FF1000TM]  77.14 62.46 270 bottom
FZ2  1A_65V_T0603FF1000TM  [F_T0603FF1000TM]  75.68 52.59 90 bottom
H1  -  [H_2P5]  369.55 71.25 0 top
H3  -  [H_3P7]  272.1 90.3 0 top
H4  -  [H_3P3]  38.85 4 0 top
H5  -  [H_3P3]  71.75 4 0 top
H6  -  [H_2P5]  3.95 71.45 0 top
H7  -  [H_2P5]  172.1 72.4 0 top
H8  -  [H_2P5]  3.6 55.25 0 top
H9  -  [H_2P5]  5.15 2.9 0 top
H10  -  [H_2P5]  285.65 61.7 0 top
H11  -  [H_2P5]  168.65 3.4 0 top
H12  -  [H_3P7]  270.6 115.1 0 top
H13  -  [H_5P0X2P5N]  370.14 2.9 0 top
H14  -  [H_3P3]  121.15 47.9 0 top
H15  -  [H_3P3]  87.35 47.9 0 top
H16  -  [H_3P2]  298.75 48.05 0 top
H17  -  [H_3P2]  326.15 43.5 0 top
H18  -  [H_2P5]  223.65 146.2 0 top
H19  -  [H_3P6X2P1]  27.9 2.9 0 top
H20  -  [H_2P5]  32.95 2.9 0 top
H21  -  [H_3P7]  202.75 91.1 0 top
H22  -  [H_3P7]  205.25 118.6 0 top
H23  -  [H_2P5]  3.95 39.05 0 top
H24  -  [H_2P1]  332.9 2.9 0 top
H25  -  [H_2P5]  69.55 54.15 0 top
H26  -  [H_2P5]  361.65 70.1 0 top
H27  -  [H_2P5]  11.65 70.1 0 top
H28  -  [H_3P3]  45.15 46.95 0 top
JAPS1  ACES_50506-01841-P01  [ACES_50506-01841-P01_18P]  13.36 5.49 0 top
JCCG1  ACES_50521-01041-P01  [ACES_50521-01041-P01_10P]  51 37.52 0 bottom
JDEG1  JXT_FP241AH-010GAAM  [JXT_FP241AH-010GAAM_10P]  55.75 3.77 0 bottom
JDG1  BELLW_80252-0521  [BELLW_80252-0521_5P-T]  105.1 16.52 180 top
JDGFF1  UNIMI_FBGCAX011  [UNIMI_FBGCAX011_68P-T-S]  177.07 89.66 270 top
JDGFF2  UNIMI_FBGCAX011  [UNIMI_FBGCAX011_68P-T-S]  177.07 105.36 270 top
JDGFF3  UNIMI_FBGCAX011  [UNIMI_FBGCAX011_68P-T-S]  177.07 121.06 270 top
JDGFF4  UNIMI_FBGCAX011  [UNIMI_FBGCAX011_68P-T-S]  177.07 136.76 270 top
JDIMM1  ADDR0208-P001A02  [LOTES_ADDR0208-P001A_260P]  275.43 37.7 0 bottom
JDIMM2  BELLW_80888-2021  [BELLW_80888-2021_260P-T]  275.43 45.9 180 top
JDIMM3  BELLW_80888-2021  [BELLW_80888-2021_260P-T]  275.43 51.7 180 bottom
JDIMM4  ADDR0206-P001A02  [LOTES_ADDR0208-P001A_260P]  275.43 59.9 0 top
JEDP1  ACES_50398-04041-001  [ACES_50398-04041-001_40P]  94.5 43.36 0 top
JESPI  JXT_FP241AH-010GAAM  [JXT_FP241AH-010GAAM_10P]  165.42 16.46 270 bottom
JFAN1  ACES_50271-0040N-001  [ACES_50271-0040N-001_4P]  302.85 50.9 90 top
JFAN2  ACES_50271-0040N-001  [ACES_50271-0040N-001_4P]  76.7 55.4 180 top
JHP1  SINGA_2SJ3088-024111F  [SINGA_2SJ3088-024111F_6P-T]  361.15 20.7 270 top
JIO1  FOX_QT510806-3121-8H  [FOX_QT510806-3121-8H_80P-T]  65.05 6.25 180 top
JIR1  ACES_50208-0060N-P01  [ACES_50208-0060N-P01_6P]  71.1 43.91 90 top
JKBTP1  HRS_TF31-20S-0P5SH-800  [HRS_TF31-20S-0P5SH-800_20P-T]  293.66 12.18 180 top
JLED1  HRS_TF31-6S-0P5SH  [HRS_TF31-6S-0P5SH_6P-T]  312.81 10.23 0 top
JLOM1  SANTA_130456-921  [SANTA_130456-921_13P-T]  205.57 139.72 180 top
JNGFF1  BELLW_80148-4221  [BELLW_80148-4221_67P]  316.9 9.98 0 bottom
JNGFF2  LOTES_APCI0071-P001A  [LOTES_APCI0071-P001A_67P]  289.5 2.42 0 bottom
JNGFF3  BELLW_SD-80159-4221  [BELLW_SD-80159-4221_67P-T]  76.38 49.2 270 bottom
JNGFF4  LOTES_APCI0364-P001A  [LOTES_APCI0364-P001A_75P]  362.9 9.1 180 bottom
JNGFF5  BELLW_SD-80159-4221  [BELLW_SD-80159-4221_67P-T]  76.38 24.15 270 bottom
JPB1  HRS_TF31-6S-0P5SH  [HRS_TF31-6S-0P5SH_6P-T]  319.65 43.75 90 top
JRTC1  ACES_50271-0020N-001  [ACES_50271-0020N-001_2P]  324.9 7.8 0 top
JSD1  T-SOL_156-1110302600  [T-SOL_156-1110302600_19P]  31.28 14.1 270 top
JSIM1  T-SOL_159-1201300600  [T-SOL_159-1201300600_8P]  350.45 47.01 180 bottom
JSPI1  CVILU_CF5020FD0R0-05-NH  [CVILU_CF5020FD0R0-05-NH_20P]  172.48 64.02 225 bottom
JSPK1  ACES_50271-0060N-001  [ACES_50271-0060N-001_6P-T]  330.26 9.11 90 top
JTAG1  @SHORT PADS~D  [SHORTPADS]  144.15 28.06 270 top
JTS1  CVILU_CI1106M1HRG-NH  [CVILU_CI1106M1HRG-NH_6P]  82.14 37.01 180 top
JUSB1  LOTES_AUSB0022-P009A  [LOTES_AUSB0022-P009A_9P]  360.67 50.8 90 top
JUSB2  LOTES_AUSB0022-P009A  [LOTES_AUSB0022-P009A_9P]  360.67 28.8 90 top
JUSBC1  FOX_UT12113-1160D-7H~D  [FOX_UT12113-1160D-7H_48P]  7.45 49.78 90 top
JUSH1  HRS_TF31C-26S-0P5SH-800  [HRS_TF31C-26S-0P5SH-800_26P-T]  176.1 2.25 0 top
JXDP1  JXT_FP270H-061G1AM  [JXT_FP270H-061G1AM_61P]  284.55 79.25 90 top
L1  MCM1012B900F06BP_4P  [INPAQ_MCM1012B900F06BP_4P]  312.63 10.1 270 bottom
LA6  BLM15PX330SN1D_2P  [MURAT_BLM15PX330SN1D_2P]  322.9 8.32 0 top
LA7  BLM15PX330SN1D_2P  [MURAT_BLM15PX330SN1D_2P]  321.98 10.47 0 top
LA8  BLM15PX330SN1D_2P  [MURAT_BLM15PX330SN1D_2P]  321.96 13.39 0 top
LA9  BLM15PX330SN1D_2P  [MURAT_BLM15PX330SN1D_2P]  321.88 15.34 0 top
LA10  BLM15PX330SN1D_2P  [MURAT_BLM15PX330SN1D_2P]  352.24 17.96 0 top
LA11  BLM15PX330SN1D_2P  [MURAT_BLM15PX330SN1D_2P]  352.23 16.99 0 top
LA12  BLM15PX600SN1D_2P  [MURAT_BLM15PX600SN1D_2P]  342.62 14.98 0 top
LA14  BLM15PX600SN1D_2P  [MURAT_BLM15PX600SN1D_2P]  342.57 16.84 90 top
LA15  BLM15PX330SN1D_2P  [MURAT_BLM15PX330SN1D_2P]  353.28 21.38 0 top
LA16  BLM15PX330SN1D_2P  [MURAT_BLM15PX330SN1D_2P]  353.29 20.28 0 top
LA21  HCB2012VF-601T20_2P  [TAI-T_HCB2012VF-601T20_2P]  341.85 29.39 90 top
LA27  BLM15PX600SN1D_2P  [MURAT_BLM15PX600SN1D_2P]  346.97 30.05 90 top
LC1  BLM15GA750SN1D_2P  [MURAT_BLM15GA750SN1D_2P]  168.1 37.59 180 bottom
LC2  BLM15GA750SN1D_2P  [MURAT_BLM15GA750SN1D_2P]  199.54 48.83 180 top
LC3  BLM15GA750SN1D_2P  [MURAT_BLM15GA750SN1D_2P]  198.72 43.35 90 bottom
LC562  BLM18EG221TN1D_2P~D  [MURAT_BLM18EG221SN1D_2P]  207.48 108.74 90 bottom
LGA1  -  [LNG2DMTR_LGA12_2X2]  341.73 27.05 90 bottom
LH421  LQM18PN2R2NC0L_2P~D  [MURAT_BLM18EG221SN1D_2P]  194.11 51.64 90 bottom
LH423  LQM18PN2R2NC0L_2P~D  [MURAT_BLM18EG221SN1D_2P]  201.53 19.07 270 top
LI3  MCM1012B900F06BP_4P  [INPAQ_MCM1012B900F06BP_4P]  352 52.94 180 top
LI4  MCM1012B900F06BP_4P  [INPAQ_MCM1012B900F06BP_4P]  353.25 40.18 90 top
LI16  DLW21HN900HQ2L_4P  [MURAT_DLW21HN900HQ2L_4P]  301.07 10.07 180 top
LI17  DLW21HN900HQ2L_4P  [MURAT_DLW21HN900HQ2L_4P]  301.94 7.96 180 top
LL1  4.7UH_MPB201210T-4R7M-NA2_20%  [CHILI_MPB201210T-4R7M-NA2_2P]  183.86 126.81 180 bottom
LR1  2.2UH_HPC252012NF-2R2M_1.3A_20%  [TAI-T_HPC252012NF-2R2M_2P]  30.6 17.77 0 bottom
LT2  1UH_LQM18PN1R0MFHD_20%  [MURAT_LQM18PN1R0MFHD_2P]  39.27 32.27 0 top
LT10  0.6UH_MND-04ABIR60M-XGL_20%  [MAG_MND-04ABIR60M-XGL_2P]  24.65 51.31 180 bottom
LV1  BLM15PX221SN1D_2P  [MURAT_BLM15PX221SN1D_2P]  102.83 45.57 90 bottom
LV2  MCM1012B900F06BP_4P  [INPAQ_MCM1012B900F06BP_4P]  103.99 34.46 90 bottom
LV3  MCM1012B900F06BP_4P  [INPAQ_MCM1012B900F06BP_4P]  83.47 31.09 90 top
LV4  BLM18KG331SN1D_2P  [MURAT_BLM18KG331SN1D_2P]  73.37 37.98 270 top
LV5  BLM18KG331SN1D_2P  [MURAT_BLM18KG331SN1D_2P]  61.89 29.69 270 bottom
LV6  BLM18KG331SN1D_2P  [MURAT_BLM18KG331SN1D_2P]  62.02 39.2 0 bottom
LV7  BLM18KG331SN1D_2P  [MURAT_BLM18KG331SN1D_2P]  72.8 29.53 270 bottom
LV8  BLM18KG331SN1D_2P  [MURAT_BLM18KG331SN1D_2P]  65.18 27.52 180 bottom
LV9  BLM18KG331SN1D_2P  [MURAT_BLM18KG331SN1D_2P]  150.58 46.65 0 bottom
LV10  BLM18KG331SN1D_2P  [MURAT_BLM18KG331SN1D_2P]  139.77 38.17 270 top
LV11  BLM18KG331SN1D_2P  [MURAT_BLM18KG331SN1D_2P]  139.58 46.49 180 top
LV12  BLM18KG331SN1D_2P  [MURAT_BLM18KG331SN1D_2P]  150.33 37.82 270 top
LV13  BLM18KG331SN1D_2P  [MURAT_BLM18KG331SN1D_2P]  145.83 35.54 0 top
NOREF  -  []  368.9 2.9 0 top
NOREF#2  -  []  205.25 118.6 0 top
NOREF#3  -  []  202.75 91.1 0 top
NOREF#4  -  []  3.95 39.05 0 top
NOREF#5  -  []  3.6 55.25 0 top
NOREF#6  -  []  69.55 54.15 0 top
NOREF#7  -  []  278.78 120.04 0 top
NOREF#8  -  []  361.65 70.1 0 top
NOREF#9  -  []  87.35 47.9 0 top
NOREF#10  -  []  232.63 73.89 0 top
NOREF#11  -  []  11.65 70.1 0 top
NOREF#12  -  []  223.65 146.2 0 top
NOREF#13  -  []  168.65 3.4 0 top
NOREF#14  -  []  224.37 28.3 0 top
NOREF#15  -  []  5.15 2.9 0 top
NOREF#16  -  []  3.95 71.45 0 top
NOREF#17  -  []  252.95 76.69 0 top
NOREF#18  -  []  121.15 47.9 0 top
NOREF#19  -  []  332.9 2.9 0 top
NOREF#20  -  []  193.13 -55.27 0 top
NOREF#21  -  []  272.1 90.3 0 top
NOREF#22  -  []  172.1 72.4 0 top
NOREF#23  -  []  45.15 46.95 0 top
NOREF#24  -  []  218.53 74.02 0 top
NOREF#25  -  []  270.6 115.1 0 top
NOREF#26  -  []  275.91 132.94 0 top
NOREF#27  -  []  248.8 20.1 0 top
NOREF#28  -  []  285.65 61.7 0 top
NOREF#29  -  []  174.25 115.65 180 bottom
NOREF#30  -  []  71.75 4 180 bottom
NOREF#31  -  []  248.68 22.94 180 bottom
NOREF#32  -  []  174.25 99.95 180 bottom
NOREF#33  -  []  32.95 2.9 180 bottom
NOREF#34  -  []  326.15 43.5 180 bottom
NOREF#35  -  []  233.67 74.68 180 bottom
NOREF#36  -  []  298.75 48.05 180 bottom
NOREF#37  -  []  248.63 75.89 180 bottom
NOREF#38  -  []  369.55 71.25 180 bottom
NOREF#39  -  []  174.25 84.25 180 bottom
NOREF#40  -  []  174.25 131.35 180 bottom
NOREF#41  -  []  38.85 4 180 bottom
PBATT1  DEREN_40-42251-01001RHF  [DEREN_40-42251-01001RHF_10P-T]  269.2 10.97 180 bottom
PC7  100P_0402_50V8J  [C_0402]  12.57 36.58 0 bottom
PC8  1000P_0402_50V7K  [C_0402]  14.25 34.45 0 bottom
PC9  0.1U_0603_25V7K  [C_0603]  16.29 32.73 90 bottom
PC10  100P_0402_50V8J  [C_0402]  15.22 32.68 90 bottom
PC11  0.022U_0603_50V7K  [C_0603]  53.84 20.78 90 top
PC12  1500P_0402_50V7K  [C_0402]  53.57 18.4 90 top
PC13  0.1U_0402_25V6  [C_0402]  58.78 23.54 270 top
PC14  100P_0402_50V8J  [C_0402]  20.08 55.51 225 top
PC15  1000P_0402_50V7K  [C_0402]  21.58 57.02 45 top
PC16  0.1U_0603_25V7K  [C_0603]  24.41 54.33 315 top
PC17  100P_0402_50V8J  [C_0402]  26.72 54.77 315 top
PC18  0.022U_0603_50V7K  [C_0603]  45.92 20.74 90 bottom
PC19  1500P_0402_50V7K  [C_0402]  51.36 17.67 270 bottom
PC20  0.1U_0402_25V6  [C_0402]  55.04 22.33 180 bottom
PC21  0.1U_0603_25V7K  [C_0603]  93.22 15.75 90 top
PC22  10U_0805_25V6K  [C_0805]  88.18 10.6 180 top
PC23  100U_D3L_25VM_R60M  [C_T521D107M025ATE060]  90.25 12.26 90 top
PC24  4.7U_0402_6.3V6M  [C_0402]  339.05 6.99 0 bottom
PC25  2200P_0402_50V7K  [C_0402]  268.15 11.11 0 top
PC30  82P_0402_50V8J  [C_0402]  87.48 11.98 180 top
PC100  0.1U_0402_25V6  [C_0402]  118.8 5.39 90 top
PC101  22U_0603_6.3V6M  [C_0603]  95.55 3.92 270 top
PC102  22U_0603_6.3V6M  [C_0603]  98.02 3.93 270 top
PC103  22U_0603_6.3V6M  [C_0603]  99.33 3.94 270 top
PC104  22U_0603_6.3V6M  [C_0603]  94.34 3.92 270 top
PC105  22U_0603_6.3V6M  [C_0603]  100.68 3.96 270 top
PC106  22U_0603_6.3V6M  [C_0603]  96.8 3.95 270 top
PC107  10U_0805_25V6K  [C_0805]  117.49 5.53 90 top
PC108  10U_0805_25V6K  [C_0805]  115.78 5.53 90 top
PC109  680P_0402_50V7K  [C_0402]  104.09 2.85 180 top
PC110  0.1U_0603_25V7K  [C_0603]  110.68 2.99 90 top
PC111  2200P_0402_50V7K  [C_0402]  119.71 5.4 90 top
PC112  1000P_0402_50V7K  [C_0402]  112.69 10.32 90 top
PC113  4.7U_0402_6.3V6M  [C_0402]  110.53 10.83 180 top
PC114  0.1U_0402_25V6  [C_0402]  70.62 8.96 180 bottom
PC115  0.1U_0603_25V7K  [C_0603]  73.07 15.31 180 bottom
PC116  2200P_0402_50V7K  [C_0402]  70.62 8.96 180 top
PC117  10U_0805_25V6K  [C_0805]  70.51 10.26 180 top
PC118  10U_0805_25V6K  [C_0805]  70.52 10.28 180 bottom
PC119  4.7U_0402_6.3V6M  [C_0402]  65.4 16.55 180 bottom
PC120  22U_0603_6.3V6M  [C_0603]  61.45 19.72 90 bottom
PC121  22U_0603_6.3V6M  [C_0603]  62.67 19.71 90 bottom
PC122  22U_0603_6.3V6M  [C_0603]  63.89 19.73 90 bottom
PC123  22U_0603_6.3V6M  [C_0603]  62.67 19.7 90 top
PC124  22U_0603_6.3V6M  [C_0603]  63.89 19.73 90 top
PC125  22U_0603_6.3V6M  [C_0603]  61.45 19.72 90 top
PC126  680P_0402_50V7K  [C_0402]  67.07 21.3 180 top
PC127  4.7U_0402_6.3V6M  [C_0402]  65.42 15.33 180 bottom
PC128  1000P_0402_50V7K  [C_0402]  65.43 13.34 180 bottom
PC129  4.7U_0402_6.3V6M  [C_0402]  65.43 12.37 180 bottom
PC138  82P_0402_50V8J  [C_0402]  74.82 9.06 270 top
PC200  10U_0805_25V6K  [C_0805]  213.07 8.29 90 top
PC201  0.22U_0603_10V7K  [C_0603]  207.29 8.79 0 top
PC202  10U_0805_25V6K  [C_0805]  214.83 8.31 90 top
PC203  0.1U_0402_25V6  [C_0402]  220.36 10.83 0 top
PC204  2200P_0402_50V7K  [C_0402]  220.35 9.94 0 top
PC205  22U_0603_6.3V6M  [C_0603]  204.59 14.7 90 top
PC206  4.7U_0402_6.3V6M  [C_0402]  203.61 7.89 0 top
PC207  330U_D2_2VM_R9M  [C_D2]  239.73 5.43 0 top
PC208  0.033U_0402_16V7K  [C_0402]  203.14 14.86 90 top
PC209  4.7U_0402_6.3V6M  [C_0402]  199.43 7.8 270 top
PC210  680P_0402_50V7K  [C_0402]  233.28 10.08 0 top
PC211  220P_0402_50V8J  [C_0402]  200.46 15.73 0 top
PC212  .1U_0402_16V7K  [C_0402]  202.26 14.86 90 top
PC213  4.7U_0402_6.3V6M  [C_0402]  200.34 11.2 180 top
PC300  2200P_0402_50V7K  [C_0402]  274.91 95.89 270 bottom
PC301  680P_0402_50V7K  [C_0402]  276.77 106.99 90 bottom
PC302  0.1U_0402_25V6  [C_0402]  275.81 95.9 270 bottom
PC303  10U_0805_25V6K  [C_0805]  278.82 95.76 270 bottom
PC304  10U_0805_25V6K  [C_0805]  277.11 95.77 270 bottom
PC305  0.1U_0603_25V7K  [C_0603]  278.05 101.85 180 bottom
PC307  22U_0603_6.3V6M  [C_0603]  274.56 109.56 90 top
PC308  22U_0603_6.3V6M  [C_0603]  275.77 109.56 90 top
PC309  22U_0603_6.3V6M  [C_0603]  275.77 109.56 90 bottom
PC310  22U_0603_6.3V6M  [C_0603]  274.56 109.56 90 bottom
PC312  0.1U_0402_25V6  [C_0402]  269.25 97.9 180 top
PC313  4.7U_0402_6.3V6M  [C_0402]  274.4 99.7 270 top
PC314  82P_0402_50V8J  [C_0402]  273.98 96.41 270 bottom
PC400  10U_0603_6.3V6M  [C_0603]  286.62 44.72 90 top
PC401  0.1U_0402_16V7K  [C_0402]  282.96 49.44 180 top
PC402  68P_0402_50V8J  [C_0402]  281.84 46.48 0 top
PC403  22U_0603_6.3V6M  [C_0603]  283.33 54.87 180 top
PC404  22U_0603_6.3V6M  [C_0603]  283.35 53.65 180 top
PC405  680P_0402_50V7K  [C_0402]  288.48 51.61 90 top
PC406  10U_0603_6.3V6M  [C_0603]  287.83 44.72 90 top
PC500  0.1U_0402_25V6  [C_0402]  316.04 37.63 90 top
PC501  0.1U_0603_25V7K  [C_0603]  307.84 34.42 90 top
PC502  2200P_0402_50V7K  [C_0402]  316.93 37.63 90 top
PC503  10U_0805_25V6K  [C_0805]  314.65 36.99 90 top
PC504  10U_0805_25V6K  [C_0805]  312.92 36.99 90 top
PC505  4.7U_0402_6.3V6M  [C_0402]  307.63 41.97 180 top
PC506  22U_0603_6.3V6M  [C_0603]  297.95 35.24 180 top
PC507  22U_0603_6.3V6M  [C_0603]  292.35 41.73 90 top
PC508  22U_0603_6.3V6M  [C_0603]  294.8 41.73 90 top
PC509  22U_0603_6.3V6M  [C_0603]  293.58 41.73 90 top
PC510  22U_0603_6.3V6M  [C_0603]  296.04 41.73 90 top
PC511  22U_0603_6.3V6M  [C_0603]  297.25 41.73 90 top
PC512  680P_0402_50V7K  [C_0402]  297.95 44.25 180 top
PC513  4.7U_0402_6.3V6M  [C_0402]  309.07 42.17 90 top
PC514  1000P_0402_50V7K  [C_0402]  311.06 42.68 90 top
PC515  4.7U_0402_6.3V6M  [C_0402]  311.53 33.71 0 top
PC520  22U_0603_6.3V6M  [C_0603]  295.52 32.16 90 top
PC521  22U_0603_6.3V6M  [C_0603]  299.35 25.79 180 top
PC522  22U_0603_6.3V6M  [C_0603]  299.19 32.15 90 top
PC523  22U_0603_6.3V6M  [C_0603]  294.28 32.16 90 top
PC524  0.1U_0402_25V6  [C_0402]  317.39 27.28 90 top
PC525  22U_0603_6.3V6M  [C_0603]  296.74 32.16 90 top
PC526  1000P_0402_50V7K  [C_0402]  310.59 32.22 90 top
PC527  680P_0402_50V7K  [C_0402]  301.85 33.7 180 top
PC528  2200P_0402_50V7K  [C_0402]  318.32 27.29 90 top
PC529  22U_0603_6.3V6M  [C_0603]  297.96 32.15 90 top
PC530  10U_0805_25V6K  [C_0805]  315.97 27.04 90 top
PC531  0.1U_0603_25V7K  [C_0603]  309.4 24.72 90 top
PC532  10U_0805_25V6K  [C_0805]  314.25 27.04 90 top
PC533  4.7U_0402_6.3V6M  [C_0402]  308.56 32 90 top
PC700  0.1U_0402_25V6  [C_0402]  290.64 35.96 270 top
PC701  0.1U_0402_25V6  [C_0402]  290.68 34.16 0 top
PC702  0.01U_0402_25V6  [C_0402]  292.04 35.03 90 top
PC703  0.1U_0402_25V6  [C_0402]  304.36 18.48 270 bottom
PC704  10U_0805_25V6K  [C_0805]  305.19 18.3 270 top
PC705  10U_0805_25V6K  [C_0805]  303.48 18.29 270 top
PC706  2.2U_0402_10V6K  [C_0402]  291.78 28.76 270 top
PC707  1U_0603_25V6K  [C_0603]  291.64 32.93 0 top
PC708  0.047U_0603_25V7M~D  [C_0603]  291.76 31.58 0 top
PC709  2200P_0402_25V7K  [C_0402]  286.7 34.98 90 top
PC710  2200P_0402_50V7K  [C_0402]  305.32 18.48 270 bottom
PC711  100P_0402_50V8J  [C_0402]  284.13 35.9 270 top
PC712  100P_0402_50V8J  [C_0402]  282.67 33.27 0 top
PC713  10U_0805_25V6K  [C_0805]  283.94 17.13 90 top
PC714  10U_0805_25V6K  [C_0805]  280.44 16.52 180 top
PC715  10U_0805_25V6K  [C_0805]  282.23 17.12 90 top
PC716  10U_0805_25V6K  [C_0805]  285.65 17.12 90 top
PC717  680P_0402_50V7K  [C_0402]  303.27 12.29 0 top
PC718  0.1U_0402_25V6  [C_0402]  288.19 25.98 270 top
PC719  0.1U_0402_25V6  [C_0402]  287.36 24.18 180 top
PC720  0.1U_0402_25V6  [C_0402]  285.55 24.67 90 top
PC725  0.01U_0402_25V7K  [C_0402]  308.4 14.17 180 bottom
PC800  0.1U_0402_25V6  [C_0402]  142.25 4.94 90 bottom
PC801  2200P_0402_50V7K  [C_0402]  141.32 4.94 90 bottom
PC802  4.7U_0805_25V6K~D  [C_0805]  143.46 5.74 90 top
PC803  4.7U_0805_25V6K~D  [C_0805]  141.71 5.74 90 top
PC804  .1U_0603_25V7K  [C_0603]  149.97 12.13 180 top
PC805  4.7U_0402_6.3V6M  [C_0402]  149.4 13.19 180 top
PC806  330U_D2_2VM_R9M  [C_D2]  161.54 9.28 270 top
PC807  0.047U_0402_25V7K  [C_0402]  156.41 11.17 0 top
PC808  680P_0402_50V7K  [C_0402]  142.33 10.9 270 top
PC900  10U_0603_6.3V6M  [C_0603]  126.57 3.98 270 top
PC901  10U_0603_6.3V6M  [C_0603]  125.37 3.99 270 top
PC902  0.1U_0402_16V7K  [C_0402]  129.78 7.29 90 top
PC903  680P_0402_50V7K  [C_0402]  134 7.28 0 top
PC904  68P_0402_50V8J  [C_0402]  127.37 8.2 270 top
PC905  22U_0603_6.3V6M  [C_0603]  137.77 5.27 90 top
PC906  22U_0603_6.3V6M  [C_0603]  136.57 5.26 90 top
PC1100  1000P_0402_50V7K  [C_0402]  261.22 151.23 270 top
PC1101  10U_0402_6.3V6M  [C_0402]  264.97 151.02 270 bottom
PC1102  0.01UF_0402_25V7K  [C_0402]  262.1 151.22 0 top
PC1103  1000P_0402_50V7K  [C_0402]  255.5 150.67 90 top
PC1104  2200P_0402_50V7K  [C_0402]  262.1 150.33 0 top
PC1105  1000P_0402_50V7K  [C_0402]  256.37 149.8 0 top
PC1106  470P_0402_50V8J  [C_0402]  264.04 147.48 90 bottom
PC1107  0.015U_0402_25V7K  [C_0402]  258.47 150.11 0 top
PC1108  100P_0402_50V8J  [C_0402]  259.37 151.9 270 top
PC1109  1000P_0402_50V7K  [C_0402]  257.33 148.06 90 bottom
PC1110  2200P_0402_50V7K  [C_0402]  259.11 148.06 90 bottom
PC1111  1000P_0402_50V7K  [C_0402]  270.17 148.7 270 top
PC1112  2200P_0402_50V7K  [C_0402]  268.38 147.8 0 top
PC1113  15P_0402_50V8J  [C_0402]  257.68 146.83 180 top
PC1114  470P_0402_50V8J  [C_0402]  255.87 148.61 0 top
PC1115  2200P_0402_50V7K  [C_0402]  255.89 145.93 90 top
PC1116  470P_0402_50V8J  [C_0402]  271.05 146.92 270 top
PC1117  15P_0402_50V8J  [C_0402]  269.28 146.03 270 top
PC1118  470P_0402_50V8J  [C_0402]  260.53 145.94 180 bottom
PC1119  2200P_0402_50V7K  [C_0402]  271.07 145.13 180 top
PC1120  470P_0402_50V8J  [C_0402]  267.07 145.82 180 bottom
PC1121  56P_0402_50V8J  [C_0402]  256.77 144.18 270 top
PC1122  1000P_0402_50V7K  [C_0402]  257.66 143.26 90 top
PC1123  0.22U_0402_25V6K  [C_0402]  260.53 144.17 180 bottom
PC1124  100P_0402_50V8J  [C_0402]  269.92 142.4 270 top
PC1125  1000P_0402_50V7K  [C_0402]  270.81 142.4 270 top
PC1126  0.22U_0402_25V6K  [C_0402]  267.07 144.93 180 bottom
PC1127  0.1U_0402_25V6  [C_0402]  260.06 139.51 270 bottom
PC1128  0.01U_0402_50V7K  [C_0402]  260.95 138.59 90 bottom
PC1129  0.1U_0402_25V6  [C_0402]  267.07 144.04 180 bottom
PC1130  4.7U_0402_6.3V6M  [C_0402]  261.85 139.51 270 bottom
PC1131  0.1U_0402_25V6  [C_0402]  258.79 140.82 180 top
PC1132  0.1U_0402_25V6  [C_0402]  267.84 142.72 270 bottom
PC1133  0.1U_0402_25V6  [C_0402]  258.79 139.68 180 top
PC1135  0.1U_0402_25V6  [C_0402]  258.79 138.41 180 top
PC1136  0.1U_0402_25V6  [C_0402]  258.66 144.12 180 bottom
PC1137  3300P_0402_50V7K~D  [C_0402]  261.88 148.37 270 bottom
PC1140  2200P_0402_50V7K  [C_0402]  256.37 152.46 0 top
PC1204  100U_D3L_25VM_R60M  [C_T521D107M025ATE060]  231.59 140.54 90 bottom
PC1205  100U_D3L_25VM_R60M  [C_T521D107M025ATE060]  245.94 140.29 90 bottom
PC1206  2200P_0402_50V7K  [C_0402]  252.31 144.48 90 top
PC1207  0.1U_0402_25V7K  [C_0402]  252.31 144.48 90 bottom
PC1208  10U_0805_25VAK  [C_0805]  249.2 144.19 90 bottom
PC1209  10U_0805_25VAK  [C_0805]  250.97 144.19 90 top
PC1210  10U_0805_25VAK  [C_0805]  250.97 144.19 90 bottom
PC1211  10U_0805_25VAK  [C_0805]  249.2 144.19 90 top
PC1213  1U_0603_16V7K  [C_0603]  251.5 142.23 180 top
PC1214  0.22U_0603_25V7K  [C_0603]  247.74 142.35 270 top
PC1215  2.2U_0603_10V7K  [C_0603]  252.61 140.94 90 top
PC1216  1000P_0603_50V7K  [C_0603]  252.27 133.05 90 bottom
PC1217  2200P_0402_50V7K  [C_0402]  242.38 144.73 90 bottom
PC1218  0.1U_0402_25V7K  [C_0402]  242.38 144.73 90 top
PC1219  10U_0805_25VAK  [C_0805]  241.02 144.4 90 top
PC1220  10U_0805_25VAK  [C_0805]  239.29 144.39 90 bottom
PC1221  10U_0805_25VAK  [C_0805]  241.02 144.4 90 bottom
PC1222  10U_0805_25VAK  [C_0805]  239.3 144.39 90 top
PC1223  1U_0603_16V7K  [C_0603]  243.76 142.02 180 top
PC1224  0.22U_0603_25V7K  [C_0603]  239.93 142.15 270 top
PC1225  2.2U_0603_10V7K  [C_0603]  244.85 140.73 90 top
PC1226  1000P_0603_50V7K  [C_0603]  244.63 133.07 90 bottom
PC1227  2200P_0402_50V7K  [C_0402]  237.96 144.73 90 top
PC1228  0.1U_0402_25V7K  [C_0402]  237.96 144.72 90 bottom
PC1229  10U_0805_25VAK  [C_0805]  234.87 144.32 90 bottom
PC1230  10U_0805_25VAK  [C_0805]  236.58 144.33 90 bottom
